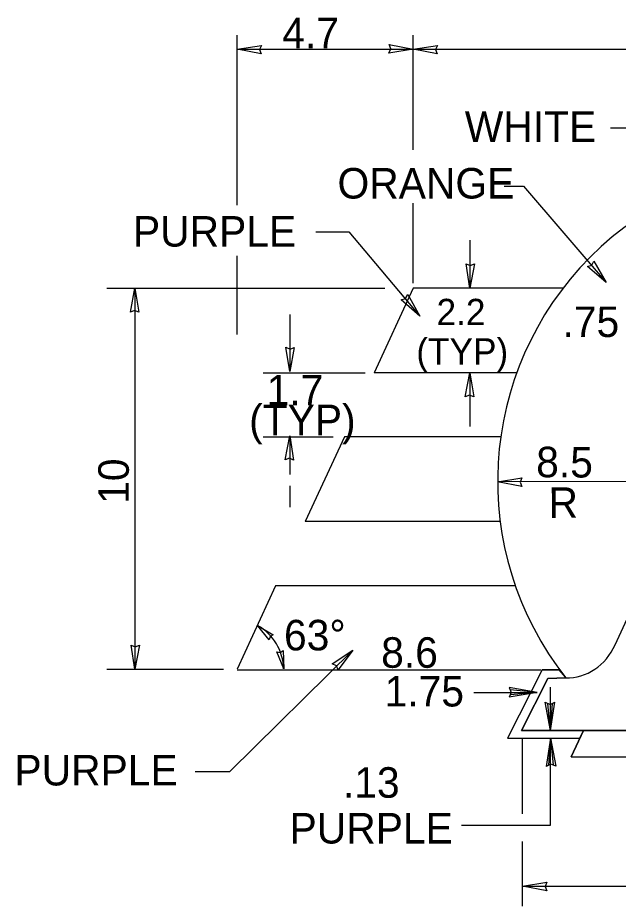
# Model space of a CAD drawing. Extents: x 10268197 to 10269179, y 2141503 to 2142677.
# Drawn here: x 10268490.2 to 10268503.98, y 2142001.64 to 2142022.02 of the extents above; entities that cross this region are included whole.
import ezdxf

# ---------------------------------------------------------------- set-up
doc = ezdxf.new("R2010")
doc.units = 0
for name, color, linetype in [('1', 7, 'Continuous'), ('52', 7, 'Continuous'), ('56', 7, 'Continuous'), ('NonPlottingEle_dp', 7, 'Continuous'), ('North Arrow', 7, 'Continuous')]:
    doc.layers.add(name, color=color, linetype=linetype)

msp = doc.modelspace()

# ---------------------------------------------------------------- linework, layer by layer
at = {"layer": '1'}
for p, q in [((10268495.235, 2142017.726), (10268495.235, 2142021.62)), ((10268499.274, 2142018.992), (10268499.274, 2142021.62)), ((10268495.235, 2142021.299), (10268499.274, 2142021.299)), ((10268499.274, 2142021.299), (10268540.97, 2142021.299)), ((10268499.274, 2142015.933), (10268499.274, 2142017.769)), ((10268500.577, 2142016.921), (10268500.577, 2142015.822)), ((10268495.235, 2142014.755), (10268495.235, 2142016.559)), ((10268492.244, 2142015.822), (10268498.624, 2142015.822)), ((10268492.891, 2142015.822), (10268492.891, 2142011.436)), ((10268499.274, 2142015.822), (10268498.377, 2142013.88)), ((10268502.715, 2142015.822), (10268499.274, 2142015.822)), ((10268496.441, 2142015.218), (10268496.441, 2142013.907)), ((10268495.834, 2142013.88), (10268498.171, 2142013.88)), ((10268501.65, 2142013.88), (10268498.377, 2142013.88)), ((10268500.577, 2142013.88), (10268500.577, 2142012.645)), ((10268495.834, 2142012.406), (10268497.441, 2142012.406)), ((10268496.441, 2142012.433), (10268496.441, 2142011.542)), ((10268497.697, 2142012.406), (10268496.799, 2142010.463)), ((10268501.283, 2142012.406), (10268497.697, 2142012.406)), ((10268492.891, 2142011.436), (10268492.891, 2142007.077)), ((10268508.5, 2142011.389), (10268501.211, 2142011.378)), ((10268496.441, 2142011.283), (10268496.441, 2142010.795)), ((10268501.272, 2142010.463), (10268496.799, 2142010.463)), ((10268496.119, 2142008.99), (10268495.235, 2142007.077)), ((10268501.598, 2142008.99), (10268496.119, 2142008.99)), ((10268495.066, 2142004.73), (10268497.886, 2142007.513)), ((10268492.244, 2142007.077), (10268494.925, 2142007.077)), ((10268495.235, 2142007.065), (10268502.206, 2142007.065)), ((10268502.425, 2142005.676), (10268502.425, 2142006.666)), ((10268500.663, 2142006.543), (10268502.12, 2142006.543)), ((10268502.425, 2142005.735), (10268502.425, 2142006.368)), ((10268503.181, 2142005.676), (10268502.902, 2142005.072)), ((10268503.121, 2142005.548), (10268503.181, 2142005.676)), ((10268511.018, 2142005.676), (10268503.181, 2142005.676)), ((10268501.784, 2142003.758), (10268501.784, 2142005.487)), ((10268502.425, 2142003.504), (10268502.425, 2142005.497)), ((10268502.902, 2142005.072), (10268511.557, 2142005.072)), ((10268494.272, 2142004.73), (10268495.066, 2142004.73)), ((10268500.383, 2142003.504), (10268502.425, 2142003.504)), ((10268501.784, 2142001.641), (10268501.784, 2142003.125)), ((10268501.784, 2142002.103), (10268511.018, 2142002.103))]:
    msp.add_line(p, q, dxfattribs=at)
for points in [[(10268503.804, 2142019.493), (10268504.282, 2142019.493), (10268507.713, 2142016.27)], [(10268501.364, 2142018.158), (10268501.803, 2142018.158), (10268503.701, 2142015.95)], [(10268497.04, 2142017.11), (10268497.8, 2142017.11), (10268499.424, 2142015.179)]]:
    msp.add_lwpolyline(points, dxfattribs=at)
msp.add_arc((10268495.142, 2142007.067), 1.158, 0.8256, 61.0937, dxfattribs=at)
at = {"layer": '52'}
for p, q in [((10268502.12, 2142006.543), (10268501.476, 2142006.662)), ((10268501.476, 2142006.662), (10268501.524, 2142006.547)), ((10268501.524, 2142006.547), (10268501.474, 2142006.434)), ((10268502.12, 2142006.543), (10268501.474, 2142006.434)), ((10268502.12, 2142006.543), (10268501.501, 2142006.602)), ((10268502.12, 2142006.543), (10268501.501, 2142006.494)), ((10268502.425, 2142005.676), (10268502.3, 2142006.319)), ((10268502.3, 2142006.319), (10268502.414, 2142006.271)), ((10268502.425, 2142005.676), (10268502.36, 2142006.294)), ((10268502.414, 2142006.271), (10268502.527, 2142006.323)), ((10268502.425, 2142005.676), (10268502.527, 2142006.323)), ((10268502.425, 2142005.676), (10268502.468, 2142006.295)), ((10268502.425, 2142005.497), (10268502.322, 2142004.85)), ((10268502.425, 2142005.497), (10268502.381, 2142004.877)), ((10268502.425, 2142005.497), (10268502.549, 2142004.853)), ((10268502.425, 2142005.497), (10268502.489, 2142004.878)), ((10268502.435, 2142004.901), (10268502.322, 2142004.85)), ((10268502.549, 2142004.853), (10268502.435, 2142004.901))]:
    msp.add_line(p, q, dxfattribs=at)
for points in [[(10268495.235, 2142021.299), (10268495.791, 2142021.387), (10268495.749, 2142021.291), (10268495.787, 2142021.193)], [(10268499.274, 2142021.299), (10268498.717, 2142021.211), (10268498.759, 2142021.307), (10268498.721, 2142021.406)], [(10268499.274, 2142021.299), (10268499.83, 2142021.387), (10268499.788, 2142021.291), (10268499.826, 2142021.193)], [(10268503.701, 2142015.95), (10268503.272, 2142016.314), (10268503.371, 2142016.345), (10268503.422, 2142016.438)], [(10268500.577, 2142015.822), (10268500.49, 2142016.378), (10268500.585, 2142016.336), (10268500.684, 2142016.374)], [(10268492.891, 2142015.822), (10268492.979, 2142015.265), (10268492.884, 2142015.307), (10268492.785, 2142015.269)], [(10268499.424, 2142015.179), (10268498.999, 2142015.549), (10268499.098, 2142015.578), (10268499.15, 2142015.671)], [(10268496.441, 2142013.907), (10268496.353, 2142014.464), (10268496.448, 2142014.422), (10268496.547, 2142014.46)], [(10268500.577, 2142013.88), (10268500.665, 2142013.323), (10268500.569, 2142013.365), (10268500.47, 2142013.327)], [(10268496.441, 2142012.433), (10268496.528, 2142011.876), (10268496.433, 2142011.918), (10268496.334, 2142011.88)], [(10268501.211, 2142011.378), (10268501.768, 2142011.467), (10268501.726, 2142011.371), (10268501.764, 2142011.272)], [(10268495.702, 2142008.081), (10268496.064, 2142007.863), (10268495.994, 2142007.828), (10268495.968, 2142007.754)], [(10268492.891, 2142007.077), (10268492.804, 2142007.633), (10268492.899, 2142007.591), (10268492.998, 2142007.629)], [(10268496.303, 2142007.085), (10268496.149, 2142007.479), (10268496.226, 2142007.462), (10268496.292, 2142007.507)], [(10268497.886, 2142007.513), (10268497.552, 2142007.06), (10268497.515, 2142007.157), (10268497.418, 2142007.201)], [(10268501.784, 2142002.103), (10268502.341, 2142002.19), (10268502.299, 2142002.095), (10268502.337, 2142001.996)]]:
    msp.add_lwpolyline(points, close=True, dxfattribs=at)
at = {"layer": '56'}
msp.add_lwpolyline([(10268499.417, 2142015.181), (10268499.424, 2142015.179), (10268499.417, 2142015.184), (10268499.419, 2142015.183), (10268499.419, 2142015.183), (10268499.419, 2142015.183), (10268499.421, 2142015.181), (10268499.419, 2142015.182), (10268499.421, 2142015.181), (10268499.417, 2142015.182), (10268499.419, 2142015.181), (10268499.417, 2142015.181), (10268499.417, 2142015.181), (10268499.419, 2142015.182), (10268499.417, 2142015.184)], dxfattribs=at)
msp.add_lwpolyline([(10268499.417, 2142015.181), (10268499.424, 2142015.179), (10268499.417, 2142015.184), (10268499.419, 2142015.183), (10268499.419, 2142015.183), (10268499.419, 2142015.183), (10268499.421, 2142015.181), (10268499.419, 2142015.182), (10268499.421, 2142015.181), (10268499.417, 2142015.182), (10268499.419, 2142015.181), (10268499.417, 2142015.181), (10268499.417, 2142015.181), (10268499.419, 2142015.182), (10268499.417, 2142015.184)], dxfattribs=at)
msp.add_lwpolyline([(10268499.417, 2142015.181), (10268499.424, 2142015.179), (10268499.417, 2142015.184), (10268499.419, 2142015.183), (10268499.419, 2142015.183), (10268499.419, 2142015.183), (10268499.421, 2142015.181), (10268499.419, 2142015.182), (10268499.421, 2142015.181), (10268499.417, 2142015.182), (10268499.419, 2142015.181), (10268499.417, 2142015.181), (10268499.417, 2142015.181), (10268499.419, 2142015.182), (10268499.417, 2142015.184)], dxfattribs=at)
at = {"layer": 'NonPlottingEle_dp'}
msp.add_lwpolyline([(10268502.625, 2142007.065), (10268502.233, 2142007.065), (10268501.435, 2142005.497), (10268503.098, 2142005.497), (10268503.181, 2142005.676), (10268501.759, 2142005.676), (10268502.364, 2142006.865), (10268502.787, 2142006.877), (10268502.769, 2142006.897)], close=True, dxfattribs=at)
at = {"layer": 'North Arrow'}
for p, q in [((10268503.908, 2142007.636), (10268507.382, 2142015.217)), ((10268502.233, 2142007.065), (10268501.435, 2142005.497)), ((10268502.233, 2142007.065), (10268502.637, 2142007.065)), ((10268502.364, 2142006.865), (10268501.759, 2142005.676)), ((10268502.776, 2142006.877), (10268502.364, 2142006.865)), ((10268501.759, 2142005.676), (10268511.018, 2142005.676)), ((10268502.902, 2142005.072), (10268503.181, 2142005.676)), ((10268501.435, 2142005.497), (10268503.098, 2142005.497)), ((10268502.902, 2142005.072), (10268511.557, 2142005.072))]:
    msp.add_line(p, q, dxfattribs=at)
msp.add_arc((10268508.5, 2142011.389), 7.288, 51.9618, 218.2529, dxfattribs=at)
msp.add_ellipse((10268502.799, 2142008.266), major_axis=(0, 1.387), ratio=0.897229, start_param=3.121696, end_param=4.241135, dxfattribs=at)

# ---------------------------------------------------------------- texts
at = {"layer": '1'}
for s, height, p in [('4.7', 0.7, (10268496.27, 2142021.321)), ('WHITE', 0.7, (10268500.458, 2142019.174)), ('ORANGE', 0.7, (10268497.538, 2142017.875)), ('PURPLE', 0.7, (10268492.845, 2142016.772)), ('2.2', 0.6037, (10268499.81, 2142014.97)), ('.75', 0.7, (10268502.7, 2142014.698)), ('(TYP)', 0.6037, (10268499.346, 2142014.066)), ('1.7', 0.7, (10268495.913, 2142013.129)), ('(TYP)', 0.7, (10268495.51, 2142012.446)), ('63°', 0.7, (10268496.31, 2142007.51)), ('8.6', 0.7, (10268498.539, 2142007.111)), ('1.75', 0.7, (10268498.618, 2142006.223)), ('PURPLE', 0.7, (10268490.126, 2142004.412)), ('.13', 0.7, (10268497.662, 2142004.13)), ('PURPLE', 0.7, (10268496.438, 2142003.08))]:
    msp.add_text(s, height=height, dxfattribs=at).set_placement(p)
for s, rotation, p in [('8.5', 359.5763, (10268502.094, 2142011.483)), ('10', 90, (10268492.75, 2142010.871)), ('R', 0.3852, (10268502.382, 2142010.547))]:
    msp.add_text(s, height=0.7, rotation=rotation, dxfattribs=at).set_placement(p)

doc.saveas('drawing.dxf')
